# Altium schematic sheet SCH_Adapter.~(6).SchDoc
size A
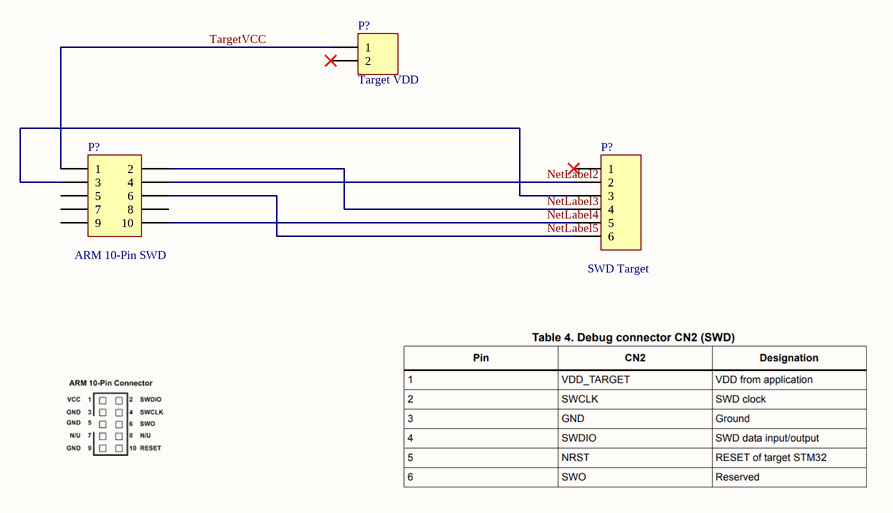
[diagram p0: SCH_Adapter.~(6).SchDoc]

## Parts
(Parts that share a designator on the sheet are numbered #1, #2 ... from top to bottom, then left to right.)
P?#1  Target VDD  [HDR1X2]
P?#2  ARM 10-Pin SWD  [HDR2X5]
P?#3  SWD Target  [HDR1X6]

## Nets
NetLabel2: P?#2.4 P?#3.2
NetLabel3: P?#2.2 P?#3.4
NetLabel4: P?#2.10 P?#3.5
NetLabel5: P?#2.6 P?#3.6
TargetVCC: P?#1.1 P?#2.1
NetP?#2_3: P?#2.3 P?#3.3

Not connected (* = marked no-connect by the designer): P?#1 2*; P?#2 5 7 8 9; P?#3 1*

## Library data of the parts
P?#1 = Header 2: Header, 2-Pin
P?#2 = Header 5X2: Header, 5-Pin, Dual row
P?#3 = Header 6: Header, 6-Pin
